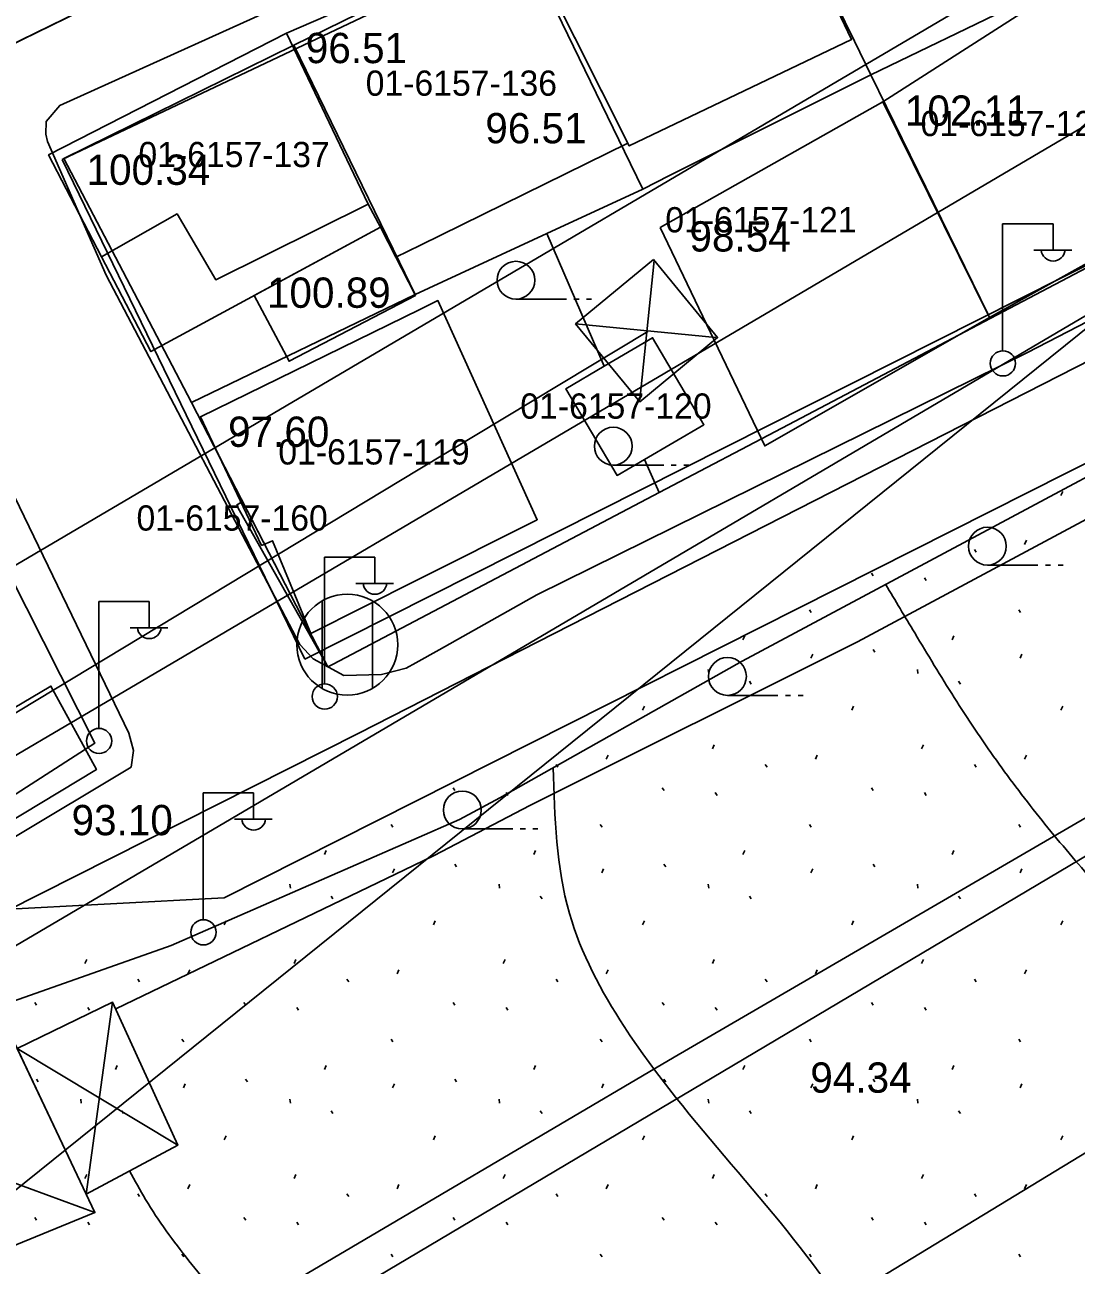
# Model space of a CAD drawing. Extents: x 412225 to 413380, y 4456471 to 4457189.
# Drawn here: x 412795.73 to 412837.41, y 4456673.13 to 4456722.27 of the extents above; entities that cross this region are included whole.
import ezdxf

# ---------------------------------------------------------------- set-up
doc = ezdxf.new("R2010")
doc.units = 0
for name, color, linetype in [('0_HALİHAZIR', 7, 'Continuous'), ('0_KADASTRO', 7, 'Continuous'), ('Level 27', 7, 'Continuous'), ('Level 28', 7, 'Continuous'), ('Level 41', 7, 'Continuous'), ('Level 54', 7, 'Continuous')]:
    doc.layers.add(name, color=color, linetype=linetype)

msp = doc.modelspace()

# ---------------------------------------------------------------- linework, layer by layer
at = {"layer": '0_HALİHAZIR'}
for p, q in [((412834.498, 4456709.382), (412834.498, 4456714.382)), ((412834.498, 4456714.382), (412836.498, 4456714.382)), ((412836.498, 4456713.382), (412836.498, 4456714.382)), ((412835.738, 4456713.342), (412837.238, 4456713.342)), ((412820.682, 4456712.93), (412820.116, 4456707.408)), ((412815.203, 4456711.403), (412817.203, 4456711.403)), ((412817.503, 4456711.403), (412817.703, 4456711.403)), ((412818.003, 4456711.403), (412818.203, 4456711.403)), ((412817.564, 4456710.424), (412823.125, 4456709.889)), ((412819.061, 4456704.828), (412821.061, 4456704.828)), ((412821.361, 4456704.828), (412821.561, 4456704.828)), ((412821.861, 4456704.828), (412822.061, 4456704.828)), ((412807.611, 4456696.182), (412807.611, 4456701.182)), ((412807.611, 4456701.182), (412809.611, 4456701.182)), ((412809.611, 4456700.182), (412809.611, 4456701.182)), ((412833.894, 4456700.864), (412835.894, 4456700.864)), ((412836.194, 4456700.864), (412836.394, 4456700.864)), ((412836.694, 4456700.864), (412836.894, 4456700.864)), ((412808.851, 4456700.142), (412810.351, 4456700.142)), ((412798.666, 4456694.422), (412798.666, 4456699.422)), ((412798.666, 4456699.422), (412800.666, 4456699.422)), ((412800.666, 4456698.422), (412800.666, 4456699.422)), ((412807.515, 4456695.981), (412807.515, 4456699.441)), ((412809.515, 4456695.981), (412809.515, 4456699.441)), ((412799.906, 4456698.382), (412801.406, 4456698.382)), ((412823.587, 4456695.704), (412825.587, 4456695.704)), ((412825.887, 4456695.704), (412826.087, 4456695.704)), ((412826.387, 4456695.704), (412826.587, 4456695.704)), ((412802.804, 4456686.839), (412802.804, 4456691.839)), ((412802.804, 4456691.839), (412804.804, 4456691.839)), ((412804.804, 4456690.839), (412804.804, 4456691.839)), ((412804.044, 4456690.799), (412805.544, 4456690.799)), ((412813.076, 4456690.411), (412815.076, 4456690.411)), ((412815.376, 4456690.411), (412815.576, 4456690.411)), ((412815.876, 4456690.411), (412816.076, 4456690.411)), ((412799.212, 4456683.547), (412798.168, 4456675.94)), ((412801.793, 4456677.881), (412795.425, 4456681.716)), ((412788.649, 4456678.813), (412798.514, 4456675.21))]:
    msp.add_line(p, q, dxfattribs=at)
for points in [[(413308.103, 4456965.941), (413265.175, 4456940.384), (413047.239, 4456812.664), (412821.475, 4456681.363)], [(412931.837, 4456800.178), (412903.863, 4456787.544), (412893.413, 4456782.904), (412892.513, 4456782.283), (412891.907, 4456781.457), (412891.837, 4456780.842), (412902.994, 4456756.704), (412906.93, 4456745.654), (412907.054, 4456744.017), (412906.977, 4456743.038), (412906.753, 4456742.155), (412906.55, 4456741.728), (412906.154, 4456741.055), (412879.555, 4456726.854), (412851.066, 4456711.433), (412824.165, 4456697.062), (412814.561, 4456691.644)], [(412816.025, 4456699.683), (412835.485, 4456709.295), (412860.277, 4456722.092), (412890.448, 4456737.159), (412902.212, 4456743.322), (412902.198, 4456743.87), (412894.314, 4456761.759), (412893.593, 4456762.996), (412893.507, 4456763.111), (412860.542, 4456748.553), (412831.808, 4456733.953), (412813.075, 4456726.17)], [(412812.813, 4456662.398), (412856.245, 4456688.806), (412912.334, 4456721.138), (412944.097, 4456732.816)], [(412773.372, 4456723.727), (412778.613, 4456727.474), (412780.161, 4456728.55), (412781.545, 4456729.4), (412782.122, 4456729.549), (412783.069, 4456728.909), (412799.855, 4456694.212), (412800.046, 4456693.522), (412799.943, 4456692.865), (412775.819, 4456678.414), (412772.83, 4456676.838)], [(412774.528, 4456716.438), (412775.763, 4456724.116), (412781.709, 4456726.636), (412792.384, 4456705.901), (412798.512, 4456693.811), (412777.295, 4456680.171)], [(412811.549, 4456724.312), (412815.41, 4456725.991), (412819.642, 4456717.578), (412811.425, 4456713.547)], [(412811.233, 4456696.989), (412810.857, 4456696.78), (412809.874, 4456696.535), (412808.379, 4456696.497), (412807.17, 4456697.153), (412806.636, 4456697.721), (412798.959, 4456712.352), (412796.63, 4456717.643), (412796.56, 4456717.938), (412796.585, 4456718.448), (412797.118, 4456719.08), (412810.72, 4456725.229), (412811.564, 4456725.566)], [(412811.425, 4456713.547), (412810.44, 4456713.064), (412809.83, 4456714.256), (412809.34, 4456715.169), (412806.101, 4456721.943), (412811.549, 4456724.312)], [(412815.749, 4456691.343), (412828.75, 4456697.822), (412847.13, 4456707.658), (412858.966, 4456714.206)], [(412820.651, 4456712.969), (412823.195, 4456709.882), (412820.109, 4456707.338), (412817.564, 4456710.424), (412820.651, 4456712.969)], [(412811.395, 4456710.998), (412812.108, 4456711.347), (412816.048, 4456702.66), (412811.271, 4456700.263)], [(412811.271, 4456700.263), (412807.074, 4456698.157), (412805.557, 4456701.833), (412805.116, 4456701.646), (412802.691, 4456706.738), (412811.395, 4456710.998)], [(412811.322, 4456704.634), (412820.427, 4456710.127)], [(412772.883, 4456681.443), (412811.322, 4456704.634)], [(412816.025, 4456699.683), (412812.161, 4456697.506), (412811.233, 4456696.989)], [(412814.561, 4456691.644), (412812.968, 4456690.791), (412811.153, 4456689.997)], [(412811.141, 4456688.967), (412811.967, 4456689.364), (412815.749, 4456691.343)], [(412811.153, 4456689.997), (412801.536, 4456685.792), (412793.703, 4456683.03), (412787.256, 4456679.961), (412781.46, 4456677.296), (412776.97, 4456675.224), (412773.019, 4456673.424), (412772.789, 4456673.309)], [(412799.334, 4456683.279), (412811.141, 4456688.967)], [(412810.982, 4456675.185), (412821.475, 4456681.363)], [(412781.087, 4456657.583), (412810.982, 4456675.185)]]:
    msp.add_lwpolyline(points, dxfattribs=at)
for points in [[(412815.41, 4456725.991), (412824.336, 4456730.445), (412828.508, 4456721.696), (412819.694, 4456717.474)], [(412838.188, 4456724.641), (412842.316, 4456715.307), (412833.98, 4456710.678), (412829.754, 4456719.226)], [(412796.671, 4456717.12), (412806.101, 4456721.943), (412809.34, 4456715.169), (412803.302, 4456712.171), (412801.768, 4456714.779), (412798.769, 4456713.075)], [(412798.769, 4456713.075), (412796.671, 4456717.12), (412806.101, 4456721.943), (412809.34, 4456715.169), (412809.83, 4456714.256), (412800.73, 4456709.323), (412798.769, 4456713.075)], [(412820.925, 4456714.242), (412825.065, 4456705.586), (412833.98, 4456710.678), (412829.754, 4456719.226)], [(412809.83, 4456714.256), (412811.217, 4456711.548), (412806.209, 4456708.943), (412804.825, 4456711.543)], [(412795.425, 4456681.716), (412799.212, 4456683.547), (412801.793, 4456677.881), (412798.168, 4456675.94)], [(412788.649, 4456678.813), (412795.36, 4456681.854), (412798.514, 4456675.21), (412792.24, 4456672.653)]]:
    msp.add_lwpolyline(points, close=True, dxfattribs=at)
for centre, radius in [((412815.203, 4456712.153), 0.75), ((412834.509, 4456708.858), 0.5), ((412819.061, 4456705.578), 0.75), ((412833.894, 4456701.614), 0.75), ((412808.515, 4456697.711), 2), ((412823.587, 4456696.454), 0.75), ((412807.622, 4456695.657), 0.5), ((412798.676, 4456693.897), 0.5), ((412813.076, 4456691.161), 0.75), ((412802.814, 4456686.315), 0.5)]:
    msp.add_circle(centre, radius, dxfattribs=at)
for centre in [(412836.499, 4456713.386), (412809.612, 4456700.185), (412800.666, 4456698.425), (412804.804, 4456690.843)]:
    msp.add_arc(centre, 0.474, 184.8384, 355.1464, dxfattribs=at)
for points in [[(412843.912, 4456681.307), (412843.757, 4456681.694), (412842.081, 4456684.075), (412840.012, 4456686.241), (412837.991, 4456688.456), (412836.059, 4456690.749), (412834.248, 4456693.133), (412832.578, 4456695.619), (412831.011, 4456698.177), (412829.858, 4456700.104)], [(412828.037, 4456671.655), (412827.986, 4456671.732), (412819.494, 4456682.578), (412817.324, 4456687.063), (412816.678, 4456692.838)], [(412813.425, 4456662.77), (412808.6, 4456666.982), (412806.368, 4456668.986), (412804.198, 4456671.055), (412802.238, 4456673.302), (412800.522, 4456675.729), (412799.888, 4456676.861)]]:
    msp.add_spline(points, degree=3, dxfattribs=at)
at = {"layer": '0_KADASTRO'}
for points in [[(412758.558, 4456668.786), (412808.977, 4456694.209), (412902.634, 4456741.974), (412909.074, 4456745.179), (412943.419, 4456762.272), (412949.024, 4456765.062), (412952.615, 4456766.849), (412963.581, 4456772.307), (412985.511, 4456783.221), (412985.536, 4456782.611), (412987.65, 4456731.4), (412981.45, 4456727.59), (412970.633, 4456720.947), (412967.171, 4456718.821), (412964.24, 4456717.02), (412920.19, 4456689.98), (412911.66, 4456684.75), (412892.499, 4456672.986), (412877.7, 4456663.9), (412867.363, 4456657.565), (412824.012, 4456630.971), (412807.183, 4456620.644)], [(412824.571, 4456729.896), (412841.883, 4456738.095), (412842.008, 4456737.863), (412846.098, 4456730.251), (412846.893, 4456728.773), (412840.926, 4456725.899), (412838.173, 4456724.573), (412834.972, 4456723.032), (412829.278, 4456720.289), (412828.625, 4456721.622)], [(412789.92, 4456731.96), (412800, 4456737.12), (412800.342, 4456736.351), (412804.924, 4456726.241), (412794.977, 4456721.371)], [(412815.331, 4456725.855), (412824.571, 4456729.896), (412828.625, 4456721.622), (412829.278, 4456720.289), (412821.29, 4456716.296), (412820.232, 4456715.767), (412819.51, 4456717.254), (412815.463, 4456725.583)], [(412806.403, 4456721.47), (412815.331, 4456725.855), (412815.463, 4456725.583), (412819.51, 4456717.254), (412820.232, 4456715.767), (412816.423, 4456714.002), (412811.206, 4456711.584), (412810.582, 4456712.869)], [(412829.278, 4456720.289), (412834.972, 4456723.032), (412838.173, 4456724.573), (412838.877, 4456723.125), (412842.675, 4456715.32), (412842.722, 4456715.224), (412834.005, 4456710.64), (412833.943, 4456710.767), (412829.896, 4456719.028)], [(412797.28, 4456716.971), (412806.403, 4456721.47), (412810.582, 4456712.869), (412811.206, 4456711.584), (412802.336, 4456707.312), (412800.502, 4456710.815)], [(412816.423, 4456714.002), (412820.232, 4456715.767), (412821.29, 4456716.296), (412829.278, 4456720.289), (412829.896, 4456719.028), (412833.943, 4456710.767), (412834.005, 4456710.64), (412826.017, 4456706.44), (412820.875, 4456703.736), (412820.303, 4456705.056), (412822.652, 4456706.425), (412820.623, 4456709.872), (412818.704, 4456708.743)], [(412802.336, 4456707.312), (412811.206, 4456711.584), (412816.423, 4456714.002), (412818.704, 4456708.743), (412817.176, 4456707.843), (412819.215, 4456704.422), (412820.303, 4456705.056), (412820.875, 4456703.736), (412807.96, 4456696.944), (412807.743, 4456696.83), (412806.488, 4456699.263), (412802.787, 4456706.437)], [(412817.176, 4456707.843), (412818.704, 4456708.743), (412820.623, 4456709.872), (412822.652, 4456706.425), (412820.303, 4456705.056), (412819.215, 4456704.422)], [(412804.125, 4456703.238), (412804.364, 4456703.38), (412806.488, 4456699.263), (412807.743, 4456696.83)], [(412774.518, 4456682.896), (412796.767, 4456696.071), (412798.57, 4456692.76), (412777.45, 4456680.03)]]:
    msp.add_lwpolyline(points, close=True, dxfattribs=at)
at = {"layer": 'Level 27'}
for p, q in [((412851.899, 4456749.229), (412795.046, 4456721.405)), ((412797.214, 4456716.94), (412824.571, 4456729.896))]:
    msp.add_line(p, q, dxfattribs=at)
at = {"layer": 'Level 28'}
for p, q in [((412851.736, 4456719.768), (412806.83, 4456697.135)), ((412806.83, 4456697.135), (412797.214, 4456716.94)), ((412803.636, 4456687.687), (412854.887, 4456713.517)), ((412790.08, 4456686.963), (412803.636, 4456687.687))]:
    msp.add_line(p, q, dxfattribs=at)
at = {"layer": 'Level 41'}
for p, q in [((412836.808, 4456703.626), (412836.88, 4456703.786)), ((412835.37, 4456701.688), (412835.441, 4456701.848)), ((412833.382, 4456701.48), (412833.453, 4456701.374)), ((412829.297, 4456700.551), (412829.368, 4456700.444)), ((412831.396, 4456700.359), (412831.467, 4456700.252)), ((412826.841, 4456699.098), (412826.912, 4456698.991)), ((412835.134, 4456699.098), (412835.205, 4456698.991)), ((412824.2, 4456697.905), (412824.271, 4456698.064)), ((412832.493, 4456697.905), (412832.564, 4456698.064)), ((412826.899, 4456697.176), (412826.971, 4456697.336)), ((412829.364, 4456697.521), (412829.435, 4456697.414)), ((412835.192, 4456697.176), (412835.264, 4456697.336)), ((412822.829, 4456696.73), (412822.847, 4456696.57)), ((412831.122, 4456696.73), (412831.14, 4456696.57)), ((412824.459, 4456696.26), (412824.529, 4456696.153)), ((412832.752, 4456696.26), (412832.822, 4456696.153)), ((412820.222, 4456695.116), (412820.294, 4456695.276)), ((412828.515, 4456695.116), (412828.587, 4456695.276)), ((412836.808, 4456695.116), (412836.88, 4456695.276)), ((412818.784, 4456693.178), (412818.855, 4456693.338)), ((412822.994, 4456693.586), (412823.064, 4456693.746)), ((412827.077, 4456693.178), (412827.148, 4456693.338)), ((412831.287, 4456693.586), (412831.357, 4456693.746)), ((412835.37, 4456693.178), (412835.441, 4456693.338)), ((412816.796, 4456692.97), (412816.867, 4456692.864)), ((412825.089, 4456692.97), (412825.16, 4456692.864)), ((412833.382, 4456692.97), (412833.453, 4456692.864)), ((412812.711, 4456692.041), (412812.782, 4456691.934)), ((412814.81, 4456691.849), (412814.881, 4456691.742)), ((412821.004, 4456692.041), (412821.075, 4456691.934)), ((412823.103, 4456691.849), (412823.174, 4456691.742)), ((412829.297, 4456692.041), (412829.368, 4456691.934)), ((412831.396, 4456691.849), (412831.467, 4456691.742)), ((412810.255, 4456690.588), (412810.326, 4456690.481)), ((412818.548, 4456690.588), (412818.619, 4456690.481)), ((412826.841, 4456690.588), (412826.912, 4456690.481)), ((412835.134, 4456690.588), (412835.205, 4456690.481)), ((412807.614, 4456689.395), (412807.685, 4456689.554)), ((412815.907, 4456689.395), (412815.978, 4456689.554)), ((412824.2, 4456689.395), (412824.271, 4456689.554)), ((412832.493, 4456689.395), (412832.564, 4456689.554)), ((412812.778, 4456689.011), (412812.849, 4456688.904)), ((412821.071, 4456689.011), (412821.142, 4456688.904)), ((412829.364, 4456689.011), (412829.435, 4456688.904)), ((412810.313, 4456688.666), (412810.385, 4456688.826)), ((412818.606, 4456688.666), (412818.678, 4456688.826)), ((412826.899, 4456688.666), (412826.971, 4456688.826)), ((412835.192, 4456688.666), (412835.264, 4456688.826)), ((412806.243, 4456688.22), (412806.261, 4456688.06)), ((412814.536, 4456688.22), (412814.554, 4456688.06)), ((412822.829, 4456688.22), (412822.847, 4456688.06)), ((412831.122, 4456688.22), (412831.14, 4456688.06)), ((412807.873, 4456687.75), (412807.943, 4456687.643)), ((412816.166, 4456687.75), (412816.236, 4456687.643)), ((412824.459, 4456687.75), (412824.529, 4456687.643)), ((412832.752, 4456687.75), (412832.822, 4456687.643)), ((412803.636, 4456686.606), (412803.708, 4456686.766)), ((412811.929, 4456686.606), (412812.001, 4456686.766)), ((412820.222, 4456686.606), (412820.294, 4456686.766)), ((412828.515, 4456686.606), (412828.587, 4456686.766)), ((412836.808, 4456686.606), (412836.88, 4456686.766)), ((412798.115, 4456685.076), (412798.185, 4456685.236)), ((412806.408, 4456685.076), (412806.478, 4456685.236)), ((412814.701, 4456685.076), (412814.771, 4456685.236)), ((412822.994, 4456685.076), (412823.064, 4456685.236)), ((412831.287, 4456685.076), (412831.357, 4456685.236)), ((412802.198, 4456684.668), (412802.269, 4456684.828)), ((412810.491, 4456684.668), (412810.562, 4456684.828)), ((412818.784, 4456684.668), (412818.855, 4456684.828)), ((412827.077, 4456684.668), (412827.148, 4456684.828)), ((412835.37, 4456684.668), (412835.441, 4456684.828)), ((412800.21, 4456684.46), (412800.281, 4456684.354)), ((412808.503, 4456684.46), (412808.574, 4456684.354)), ((412816.796, 4456684.46), (412816.867, 4456684.354)), ((412825.089, 4456684.46), (412825.16, 4456684.354)), ((412833.382, 4456684.46), (412833.453, 4456684.354)), ((412796.125, 4456683.531), (412796.196, 4456683.424)), ((412804.418, 4456683.531), (412804.489, 4456683.424)), ((412812.711, 4456683.531), (412812.782, 4456683.424)), ((412821.004, 4456683.531), (412821.075, 4456683.424)), ((412829.297, 4456683.531), (412829.368, 4456683.424)), ((412798.224, 4456683.339), (412798.295, 4456683.232)), ((412806.517, 4456683.339), (412806.588, 4456683.232)), ((412814.81, 4456683.339), (412814.881, 4456683.232)), ((412823.103, 4456683.339), (412823.174, 4456683.232)), ((412831.396, 4456683.339), (412831.467, 4456683.232)), ((412801.962, 4456682.078), (412802.033, 4456681.971)), ((412810.255, 4456682.078), (412810.326, 4456681.971)), ((412818.548, 4456682.078), (412818.619, 4456681.971)), ((412826.841, 4456682.078), (412826.912, 4456681.971)), ((412835.134, 4456682.078), (412835.205, 4456681.971)), ((412799.321, 4456680.885), (412799.392, 4456681.044)), ((412807.614, 4456680.885), (412807.685, 4456681.044)), ((412815.907, 4456680.885), (412815.978, 4456681.044)), ((412824.2, 4456680.885), (412824.271, 4456681.044)), ((412832.493, 4456680.885), (412832.564, 4456681.044)), ((412796.192, 4456680.501), (412796.263, 4456680.394)), ((412802.02, 4456680.156), (412802.092, 4456680.316)), ((412804.485, 4456680.501), (412804.556, 4456680.394)), ((412810.313, 4456680.156), (412810.385, 4456680.316)), ((412812.778, 4456680.501), (412812.849, 4456680.394)), ((412818.606, 4456680.156), (412818.678, 4456680.316)), ((412821.071, 4456680.501), (412821.142, 4456680.394)), ((412826.899, 4456680.156), (412826.971, 4456680.316)), ((412829.364, 4456680.501), (412829.435, 4456680.394)), ((412835.192, 4456680.156), (412835.264, 4456680.316)), ((412797.95, 4456679.71), (412797.968, 4456679.55)), ((412806.243, 4456679.71), (412806.261, 4456679.55)), ((412814.536, 4456679.71), (412814.554, 4456679.55)), ((412822.829, 4456679.71), (412822.847, 4456679.55)), ((412831.122, 4456679.71), (412831.14, 4456679.55)), ((412799.58, 4456679.24), (412799.65, 4456679.133)), ((412807.873, 4456679.24), (412807.943, 4456679.133)), ((412816.166, 4456679.24), (412816.236, 4456679.133)), ((412824.459, 4456679.24), (412824.529, 4456679.133)), ((412832.752, 4456679.24), (412832.822, 4456679.133)), ((412803.636, 4456678.096), (412803.708, 4456678.256)), ((412811.929, 4456678.096), (412812.001, 4456678.256)), ((412820.222, 4456678.096), (412820.294, 4456678.256)), ((412828.515, 4456678.096), (412828.587, 4456678.256)), ((412836.808, 4456678.096), (412836.88, 4456678.256)), ((412798.115, 4456676.566), (412798.185, 4456676.726)), ((412806.408, 4456676.566), (412806.478, 4456676.726)), ((412814.701, 4456676.566), (412814.771, 4456676.726)), ((412822.994, 4456676.566), (412823.064, 4456676.726)), ((412831.287, 4456676.566), (412831.357, 4456676.726)), ((412802.198, 4456676.158), (412802.269, 4456676.318)), ((412810.491, 4456676.158), (412810.562, 4456676.318)), ((412818.784, 4456676.158), (412818.855, 4456676.318)), ((412827.077, 4456676.158), (412827.148, 4456676.318)), ((412835.37, 4456676.158), (412835.441, 4456676.318)), ((412800.21, 4456675.95), (412800.281, 4456675.844)), ((412808.503, 4456675.95), (412808.574, 4456675.844)), ((412816.796, 4456675.95), (412816.867, 4456675.844)), ((412825.089, 4456675.95), (412825.16, 4456675.844)), ((412833.382, 4456675.95), (412833.453, 4456675.844)), ((412796.125, 4456675.021), (412796.196, 4456674.914)), ((412798.224, 4456674.829), (412798.295, 4456674.722)), ((412804.418, 4456675.021), (412804.489, 4456674.914)), ((412806.517, 4456674.829), (412806.588, 4456674.722)), ((412812.711, 4456675.021), (412812.782, 4456674.914)), ((412814.81, 4456674.829), (412814.881, 4456674.722)), ((412821.004, 4456675.021), (412821.075, 4456674.914)), ((412823.103, 4456674.829), (412823.174, 4456674.722)), ((412829.297, 4456675.021), (412829.368, 4456674.914)), ((412831.396, 4456674.829), (412831.467, 4456674.722)), ((412801.962, 4456673.568), (412802.033, 4456673.461)), ((412810.255, 4456673.568), (412810.326, 4456673.461)), ((412818.548, 4456673.568), (412818.619, 4456673.461)), ((412826.841, 4456673.568), (412826.912, 4456673.461)), ((412835.134, 4456673.568), (412835.205, 4456673.461))]:
    msp.add_line(p, q, dxfattribs=at)
at = {"layer": 'Level 54'}
msp.add_line((412838.075, 4456710.447), (412777.393, 4456661.653), dxfattribs=at)
for points in [[(412772.861, 4456680.089), (413040.614, 4456837.658)], [(412772.521, 4456650.705), (412780.988, 4456655.646), (413046.364, 4456813.097)], [(412769.564, 4456685.691), (412836.433, 4456725.042)], [(412776.158, 4456674.487), (412843.025, 4456713.837)]]:
    msp.add_lwpolyline(points, dxfattribs=at)

# ---------------------------------------------------------------- texts
at = {"layer": '0_HALİHAZIR'}
for s, p in [('96.51', (412806.872, 4456720.754)), ('102.11', (412830.624, 4456718.273)), ('96.51', (412813.988, 4456717.578)), ('100.34', (412798.179, 4456715.932)), ('98.54', (412822.081, 4456713.29)), ('100.89', (412805.331, 4456711.06)), ('97.60', (412803.791, 4456705.55)), ('93.10', (412797.585, 4456690.163)), ('94.34', (412826.873, 4456679.96))]:
    msp.add_text(s, height=1.2, dxfattribs=at).set_placement(p)
at = {"layer": '0_KADASTRO'}
for s, p in [('01-6157-136', (412809.247, 4456719.462)), ('01-6157-136', (412809.247, 4456719.462)), ('01-6157-122', (412831.245, 4456717.863)), ('01-6157-122', (412831.245, 4456717.863)), ('01-6157-137', (412800.236, 4456716.633)), ('01-6157-137', (412800.236, 4456716.633)), ('01-6157-121', (412821.123, 4456714.049)), ('01-6157-121', (412821.123, 4456714.049)), ('01-6157-120', (412815.375, 4456706.668)), ('01-6157-120', (412815.375, 4456706.668)), ('01-6157-119', (412805.782, 4456704.851)), ('01-6157-119', (412805.782, 4456704.851)), ('01-6157-160', (412800.159, 4456702.232)), ('01-6157-160', (412800.159, 4456702.232))]:
    msp.add_text(s, height=1, dxfattribs=at).set_placement(p)

doc.saveas('drawing.dxf')
